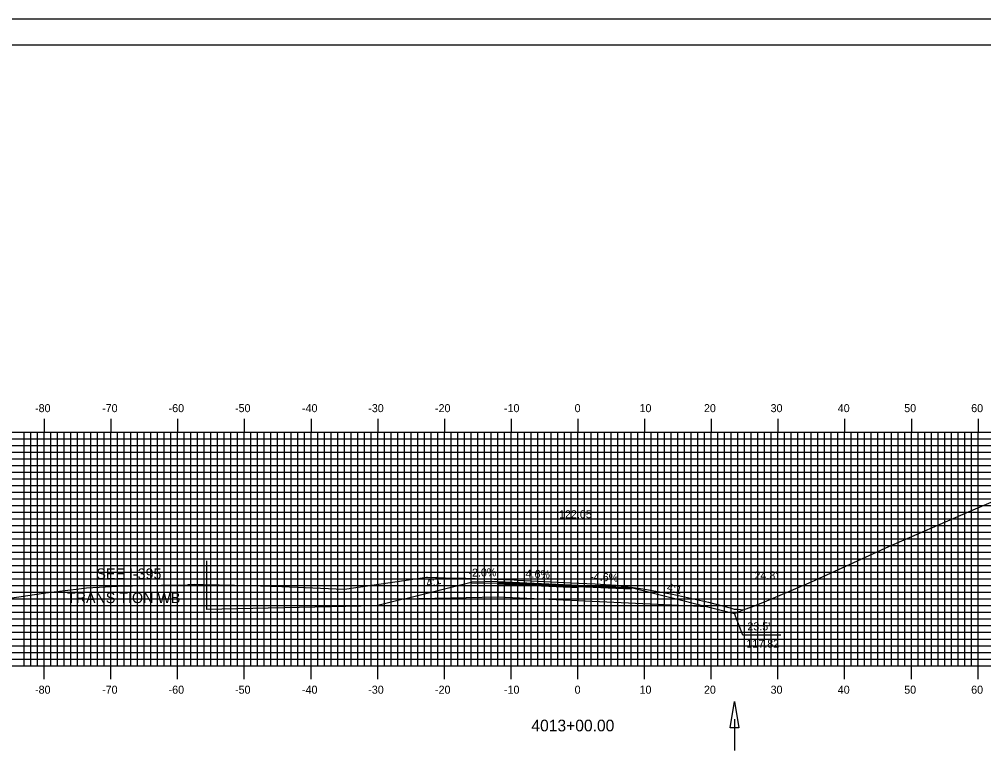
# Model space of a CAD drawing. Extents: x 852934 to 853277, y 364661 to 364881.
# Drawn here: x 853016 to 853160.6, y 364770.1 to 364881.3 of the extents above; entities that cross this region are included whole.
import ezdxf

# ---------------------------------------------------------------- set-up
doc = ezdxf.new("R2010")
doc.units = 0
for name, color, linetype in [('ANNOTATION', 7, 'Continuous'), ('BORDER', 7, 'Continuous'), ('D_Drainage_Ditch_Line', 7, 'Continuous'), ('D_Roadway_Centerline_Text', 7, 'Continuous'), ('D_Roadway_Edge_Shoulder', 7, 'Continuous'), ('D_Roadway_Edge_TW', 7, 'Continuous'), ('D_Roadway_Pavement', 7, 'Continuous'), ('D_Roadway_SubGrade', 7, 'Continuous'), ('D_Text_Standard', 7, 'Continuous'), ('H_V ANNOTATION', 7, 'Continuous'), ('M_Roadway_Centerline', 7, 'Continuous'), ('MAJOR', 7, 'Continuous'), ('MINOR', 7, 'Continuous'), ('PLOT BOUNDARY', 7, 'Continuous'), ('S_Roadway_Centerline', 7, 'Continuous')]:
    doc.layers.add(name, color=color, linetype=linetype)

msp = doc.modelspace()

# ---------------------------------------------------------------- linework, layer by layer
at = {"layer": 'ANNOTATION'}
for points in [[(853073.58, 364794.36), (853069.58, 364793.36), (853044.11, 364792.8)], [(853119.29, 364793.19), (853123.29, 364792.19), (853124.57, 364792.74)], [(853130.2, 364788.95), (853124.51, 364788.95), (853123.29, 364792.19)]]:
    msp.add_lwpolyline(points, dxfattribs=at)
at = {"layer": 'BORDER'}
msp.add_lwpolyline([(852950.18, 364667.37), (853270.18, 364667.37), (853270.18, 364877.37), (852950.18, 364877.37)], close=True, dxfattribs=at)
at = {"layer": 'D_Drainage_Ditch_Line'}
msp.add_line((853123.29, 364776.37), (853123.29, 364771.67), dxfattribs=at)
msp.add_lwpolyline([(853123.94, 364775.06), (853122.63, 364775.06), (853123.29, 364778.99)], close=True, dxfattribs=at)
at = {"layer": 'D_Roadway_Edge_Shoulder'}
for points in [[(853087.78, 364796.99), (853083.78, 364796.91), (853083.78, 364796.74), (853087.78, 364796.81)], [(853099.78, 364796.44), (853107.78, 364796.07), (853107.78, 364795.9), (853099.78, 364796.25)]]:
    msp.add_lwpolyline(points, close=True, dxfattribs=at)
at = {"layer": 'D_Roadway_Edge_TW'}
msp.add_lwpolyline([(853087.78, 364796.99), (853099.78, 364796.44), (853099.78, 364796.25), (853087.78, 364796.81)], close=True, dxfattribs=at)
at = {"layer": 'D_Roadway_Pavement'}
msp.add_lwpolyline([(853087.78, 364796.81), (853099.78, 364796.25), (853099.78, 364796.09), (853087.78, 364796.64)], close=True, dxfattribs=at)
for points in [[(853087.78, 364796.81), (853087.78, 364796.64)], [(853099.78, 364796.25), (853099.78, 364796.09)], [(853099.78, 364796.25), (853099.78, 364796.09)]]:
    msp.add_lwpolyline(points, dxfattribs=at)
at = {"layer": 'D_Roadway_SubGrade'}
msp.add_line((853044.11, 364800.1), (853044.11, 364792.8), dxfattribs=at)
for points in [[(853087.78, 364794.64), (853073.58, 364794.36), (853083.78, 364796.91), (853083.78, 364796.74), (853087.78, 364796.81), (853087.78, 364796.64)], [(853087.78, 364796.64), (853099.78, 364796.09), (853099.78, 364794.09), (853087.78, 364794.64)], [(853099.78, 364796.09), (853099.78, 364796.25), (853107.78, 364795.9), (853107.78, 364796.07), (853119.29, 364793.19), (853099.78, 364794.09)]]:
    msp.add_lwpolyline(points, close=True, dxfattribs=at)
at = {"layer": 'MAJOR'}
for p, q in [((853019.78, 364821.37), (853019.78, 364819.37)), ((853029.78, 364821.37), (853029.78, 364819.37)), ((853039.78, 364821.37), (853039.78, 364819.37)), ((853049.78, 364821.37), (853049.78, 364819.37)), ((853059.78, 364821.37), (853059.78, 364819.37)), ((853069.78, 364821.37), (853069.78, 364819.37)), ((853079.78, 364821.37), (853079.78, 364819.37)), ((853089.78, 364821.37), (853089.78, 364819.37)), ((853099.78, 364821.37), (853099.78, 364819.37)), ((853109.78, 364821.37), (853109.78, 364819.37)), ((853119.78, 364821.37), (853119.78, 364819.37)), ((853129.78, 364821.37), (853129.78, 364819.37)), ((853139.78, 364821.37), (853139.78, 364819.37)), ((853149.78, 364821.37), (853149.78, 364819.37)), ((853159.78, 364821.37), (853159.78, 364819.37)), ((852959.78, 364819.37), (853239.78, 364819.37)), ((852959.78, 364819.37), (853239.78, 364819.37)), ((853019.78, 364784.37), (853019.78, 364819.37)), ((853029.78, 364784.37), (853029.78, 364819.37)), ((853039.78, 364784.37), (853039.78, 364819.37)), ((853049.78, 364784.37), (853049.78, 364819.37)), ((853059.78, 364784.37), (853059.78, 364819.37)), ((853069.78, 364784.37), (853069.78, 364819.37)), ((853079.78, 364784.37), (853079.78, 364819.37)), ((853089.78, 364784.37), (853089.78, 364819.37)), ((853099.78, 364784.37), (853099.78, 364819.37)), ((853109.78, 364784.37), (853109.78, 364819.37)), ((853119.78, 364784.37), (853119.78, 364819.37)), ((853129.78, 364784.37), (853129.78, 364819.37)), ((853139.78, 364784.37), (853139.78, 364819.37)), ((853149.78, 364784.37), (853149.78, 364819.37)), ((853159.78, 364784.37), (853159.78, 364819.37)), ((852959.78, 364814.37), (853239.78, 364814.37)), ((852959.78, 364809.37), (853239.78, 364809.37)), ((852959.78, 364804.37), (853239.78, 364804.37)), ((852959.78, 364799.37), (853239.78, 364799.37)), ((852959.78, 364794.37), (853239.78, 364794.37)), ((852959.78, 364789.37), (853239.78, 364789.37)), ((852959.78, 364784.37), (853239.78, 364784.37)), ((852959.78, 364784.37), (853239.78, 364784.37)), ((853019.78, 364782.37), (853019.78, 364784.37)), ((853029.78, 364782.37), (853029.78, 364784.37)), ((853039.78, 364782.37), (853039.78, 364784.37)), ((853049.78, 364782.37), (853049.78, 364784.37)), ((853059.78, 364782.37), (853059.78, 364784.37)), ((853069.78, 364782.37), (853069.78, 364784.37)), ((853079.78, 364782.37), (853079.78, 364784.37)), ((853089.78, 364782.37), (853089.78, 364784.37)), ((853099.78, 364782.37), (853099.78, 364784.37)), ((853109.78, 364782.37), (853109.78, 364784.37)), ((853119.78, 364782.37), (853119.78, 364784.37)), ((853129.78, 364782.37), (853129.78, 364784.37)), ((853139.78, 364782.37), (853139.78, 364784.37)), ((853149.78, 364782.37), (853149.78, 364784.37)), ((853159.78, 364782.37), (853159.78, 364784.37))]:
    msp.add_line(p, q, dxfattribs=at)
at = {"layer": 'MINOR'}
for p, q in [((853016.78, 364784.37), (853016.78, 364819.37)), ((853017.78, 364784.37), (853017.78, 364819.37)), ((853018.78, 364784.37), (853018.78, 364819.37)), ((853020.78, 364784.37), (853020.78, 364819.37)), ((853021.78, 364784.37), (853021.78, 364819.37)), ((853022.78, 364784.37), (853022.78, 364819.37)), ((853023.78, 364784.37), (853023.78, 364819.37)), ((853024.78, 364784.37), (853024.78, 364819.37)), ((853025.78, 364784.37), (853025.78, 364819.37)), ((853026.78, 364784.37), (853026.78, 364819.37)), ((853027.78, 364784.37), (853027.78, 364819.37)), ((853028.78, 364784.37), (853028.78, 364819.37)), ((853030.78, 364784.37), (853030.78, 364819.37)), ((853031.78, 364784.37), (853031.78, 364819.37)), ((853032.78, 364784.37), (853032.78, 364819.37)), ((853033.78, 364784.37), (853033.78, 364819.37)), ((853034.78, 364784.37), (853034.78, 364819.37)), ((853035.78, 364784.37), (853035.78, 364819.37)), ((853036.78, 364784.37), (853036.78, 364819.37)), ((853037.78, 364784.37), (853037.78, 364819.37)), ((853038.78, 364784.37), (853038.78, 364819.37)), ((853040.78, 364784.37), (853040.78, 364819.37)), ((853041.78, 364784.37), (853041.78, 364819.37)), ((853042.78, 364784.37), (853042.78, 364819.37)), ((853043.78, 364784.37), (853043.78, 364819.37)), ((853044.78, 364784.37), (853044.78, 364819.37)), ((853045.78, 364784.37), (853045.78, 364819.37)), ((853046.78, 364784.37), (853046.78, 364819.37)), ((853047.78, 364784.37), (853047.78, 364819.37)), ((853048.78, 364784.37), (853048.78, 364819.37)), ((853050.78, 364784.37), (853050.78, 364819.37)), ((853051.78, 364784.37), (853051.78, 364819.37)), ((853052.78, 364784.37), (853052.78, 364819.37)), ((853053.78, 364784.37), (853053.78, 364819.37)), ((853054.78, 364784.37), (853054.78, 364819.37)), ((853055.78, 364784.37), (853055.78, 364819.37)), ((853056.78, 364784.37), (853056.78, 364819.37)), ((853057.78, 364784.37), (853057.78, 364819.37)), ((853058.78, 364784.37), (853058.78, 364819.37)), ((853060.78, 364784.37), (853060.78, 364819.37)), ((853061.78, 364784.37), (853061.78, 364819.37)), ((853062.78, 364784.37), (853062.78, 364819.37)), ((853063.78, 364784.37), (853063.78, 364819.37)), ((853064.78, 364784.37), (853064.78, 364819.37)), ((853065.78, 364784.37), (853065.78, 364819.37)), ((853066.78, 364784.37), (853066.78, 364819.37)), ((853067.78, 364784.37), (853067.78, 364819.37)), ((853068.78, 364784.37), (853068.78, 364819.37)), ((853070.78, 364784.37), (853070.78, 364819.37)), ((853071.78, 364784.37), (853071.78, 364819.37)), ((853072.78, 364784.37), (853072.78, 364819.37)), ((853073.78, 364784.37), (853073.78, 364819.37)), ((853074.78, 364784.37), (853074.78, 364819.37)), ((853075.78, 364784.37), (853075.78, 364819.37)), ((853076.78, 364784.37), (853076.78, 364819.37)), ((853077.78, 364784.37), (853077.78, 364819.37)), ((853078.78, 364784.37), (853078.78, 364819.37)), ((853080.78, 364784.37), (853080.78, 364819.37)), ((853081.78, 364784.37), (853081.78, 364819.37)), ((853082.78, 364784.37), (853082.78, 364819.37)), ((853083.78, 364784.37), (853083.78, 364819.37)), ((853084.78, 364784.37), (853084.78, 364819.37)), ((853085.78, 364784.37), (853085.78, 364819.37)), ((853086.78, 364784.37), (853086.78, 364819.37)), ((853087.78, 364784.37), (853087.78, 364819.37)), ((853088.78, 364784.37), (853088.78, 364819.37)), ((853090.78, 364784.37), (853090.78, 364819.37)), ((853091.78, 364784.37), (853091.78, 364819.37)), ((853092.78, 364784.37), (853092.78, 364819.37)), ((853093.78, 364784.37), (853093.78, 364819.37)), ((853094.78, 364784.37), (853094.78, 364819.37)), ((853095.78, 364784.37), (853095.78, 364819.37)), ((853096.78, 364784.37), (853096.78, 364819.37)), ((853097.78, 364784.37), (853097.78, 364819.37)), ((853098.78, 364784.37), (853098.78, 364819.37)), ((853100.78, 364784.37), (853100.78, 364819.37)), ((853101.78, 364784.37), (853101.78, 364819.37)), ((853102.78, 364784.37), (853102.78, 364819.37)), ((853103.78, 364784.37), (853103.78, 364819.37)), ((853104.78, 364784.37), (853104.78, 364819.37)), ((853105.78, 364784.37), (853105.78, 364819.37)), ((853106.78, 364784.37), (853106.78, 364819.37)), ((853107.78, 364784.37), (853107.78, 364819.37)), ((853108.78, 364784.37), (853108.78, 364819.37)), ((853110.78, 364784.37), (853110.78, 364819.37)), ((853111.78, 364784.37), (853111.78, 364819.37)), ((853112.78, 364784.37), (853112.78, 364819.37)), ((853113.78, 364784.37), (853113.78, 364819.37)), ((853114.78, 364784.37), (853114.78, 364819.37)), ((853115.78, 364784.37), (853115.78, 364819.37)), ((853116.78, 364784.37), (853116.78, 364819.37)), ((853117.78, 364784.37), (853117.78, 364819.37)), ((853118.78, 364784.37), (853118.78, 364819.37)), ((853120.78, 364784.37), (853120.78, 364819.37)), ((853121.78, 364784.37), (853121.78, 364819.37)), ((853122.78, 364784.37), (853122.78, 364819.37)), ((853123.78, 364784.37), (853123.78, 364819.37)), ((853124.78, 364784.37), (853124.78, 364819.37)), ((853125.78, 364784.37), (853125.78, 364819.37)), ((853126.78, 364784.37), (853126.78, 364819.37)), ((853127.78, 364784.37), (853127.78, 364819.37)), ((853128.78, 364784.37), (853128.78, 364819.37)), ((853130.78, 364784.37), (853130.78, 364819.37)), ((853131.78, 364784.37), (853131.78, 364819.37)), ((853132.78, 364784.37), (853132.78, 364819.37)), ((853133.78, 364784.37), (853133.78, 364819.37)), ((853134.78, 364784.37), (853134.78, 364819.37)), ((853135.78, 364784.37), (853135.78, 364819.37)), ((853136.78, 364784.37), (853136.78, 364819.37)), ((853137.78, 364784.37), (853137.78, 364819.37)), ((853138.78, 364784.37), (853138.78, 364819.37)), ((853140.78, 364784.37), (853140.78, 364819.37)), ((853141.78, 364784.37), (853141.78, 364819.37)), ((853142.78, 364784.37), (853142.78, 364819.37)), ((853143.78, 364784.37), (853143.78, 364819.37)), ((853144.78, 364784.37), (853144.78, 364819.37)), ((853145.78, 364784.37), (853145.78, 364819.37)), ((853146.78, 364784.37), (853146.78, 364819.37)), ((853147.78, 364784.37), (853147.78, 364819.37)), ((853148.78, 364784.37), (853148.78, 364819.37)), ((853150.78, 364784.37), (853150.78, 364819.37)), ((853151.78, 364784.37), (853151.78, 364819.37)), ((853152.78, 364784.37), (853152.78, 364819.37)), ((853153.78, 364784.37), (853153.78, 364819.37)), ((853154.78, 364784.37), (853154.78, 364819.37)), ((853155.78, 364784.37), (853155.78, 364819.37)), ((853156.78, 364784.37), (853156.78, 364819.37)), ((853157.78, 364784.37), (853157.78, 364819.37)), ((853158.78, 364784.37), (853158.78, 364819.37)), ((852959.78, 364818.37), (853239.78, 364818.37)), ((852959.78, 364817.37), (853239.78, 364817.37)), ((852959.78, 364816.37), (853239.78, 364816.37)), ((852959.78, 364815.37), (853239.78, 364815.37)), ((852959.78, 364813.37), (853239.78, 364813.37)), ((852959.78, 364812.37), (853239.78, 364812.37)), ((852959.78, 364811.37), (853239.78, 364811.37)), ((852959.78, 364810.37), (853239.78, 364810.37)), ((852959.78, 364808.37), (853239.78, 364808.37)), ((852959.78, 364807.37), (853239.78, 364807.37)), ((852959.78, 364806.37), (853239.78, 364806.37)), ((852959.78, 364805.37), (853239.78, 364805.37)), ((852959.78, 364803.37), (853239.78, 364803.37)), ((852959.78, 364802.37), (853239.78, 364802.37)), ((852959.78, 364801.37), (853239.78, 364801.37)), ((852959.78, 364800.37), (853239.78, 364800.37)), ((852959.78, 364798.37), (853239.78, 364798.37)), ((852959.78, 364797.37), (853239.78, 364797.37)), ((852959.78, 364796.37), (853239.78, 364796.37)), ((852959.78, 364795.37), (853239.78, 364795.37)), ((852959.78, 364793.37), (853239.78, 364793.37)), ((852959.78, 364792.37), (853239.78, 364792.37)), ((852959.78, 364791.37), (853239.78, 364791.37)), ((852959.78, 364790.37), (853239.78, 364790.37)), ((852959.78, 364788.37), (853239.78, 364788.37)), ((852959.78, 364787.37), (853239.78, 364787.37)), ((852959.78, 364786.37), (853239.78, 364786.37)), ((852959.78, 364785.37), (853239.78, 364785.37))]:
    msp.add_line(p, q, dxfattribs=at)
at = {"layer": 'PLOT BOUNDARY'}
msp.add_lwpolyline([(852933.99, 364661.25), (853273.99, 364661.25), (853273.99, 364881.25), (852933.99, 364881.25)], close=True, dxfattribs=at)
at = {"layer": 'S_Roadway_Centerline'}
msp.add_lwpolyline([(853014.3, 364794.43), (853020.03, 364795.3), (853024.96, 364795.9), (853026.11, 364796.04), (853030.83, 364796.29), (853037.34, 364796.45), (853041.28, 364796.51), (853041.43, 364796.55), (853042.33, 364796.57), (853043.7, 364796.54), (853050.63, 364796.37), (853055.38, 364796.26), (853063.57, 364795.91), (853064.75, 364795.86), (853064.81, 364795.84), (853074.39, 364797.22), (853077.08, 364797.63), (853077.24, 364797.65), (853079.91, 364797.56), (853081.83, 364797.5), (853083, 364797.47), (853088.63, 364797.28), (853090.24, 364797.22), (853090.68, 364797.18), (853098.66, 364796.8), (853102.37, 364796.62), (853105.52, 364796.43), (853109.51, 364795.87), (853113.97, 364795.08), (853119.35, 364793.89), (853122.64, 364793.03), (853123.2, 364792.86), (853123.81, 364792.85), (853124.57, 364792.74), (853125.87, 364793.2), (853127.74, 364793.94), (853134.8, 364796.92), (853146.39, 364802.23), (853158.35, 364807.45), (853168.78, 364811.88)], dxfattribs=at)

# ---------------------------------------------------------------- texts
at = {"layer": 'ANNOTATION'}
for s, height, p in [('SEE I-395 ', 1.6, (853027.6, 364797.35)), ('TRANSITION WB', 1.6, (853023.19, 364793.75)), ("23.5' ", 1.2, (853125.2, 364789.67)), ('117.82', 1.2, (853125.05, 364787.07))]:
    msp.add_text(s, height=height, dxfattribs=at).set_placement(p)
for s, rotation, p in [('-2.0%', 1.1458, (853083.39, 364797.7)), ('4.6%', 357.3663, (853091.93, 364797.6)), ('4:1', 14.0362, (853077.21, 364796.13)), ('-4.6%', 357.3663, (853101.61, 364797.15)), ('4:1', 345.9638, (853113.04, 364795.61))]:
    msp.add_text(s, height=1.2, rotation=rotation, dxfattribs=at).set_placement(p)
at = {"layer": 'D_Roadway_Centerline_Text'}
msp.add_text('122.05', height=1.2, dxfattribs=at).set_placement((853096.96, 364806.47))
at = {"layer": 'D_Text_Standard'}
msp.add_text("24.8'", height=1.2, dxfattribs=at).set_placement((853126.26, 364797.31))
at = {"layer": 'H_V ANNOTATION'}
for s, height, p in [('-80', 1.2, (853018.41, 364822.37)), ('-70', 1.2, (853028.46, 364822.37)), ('-60', 1.2, (853038.43, 364822.37)), ('-50', 1.2, (853048.39, 364822.37)), ('-40', 1.2, (853058.43, 364822.37)), ('-30', 1.2, (853068.36, 364822.37)), ('-20', 1.2, (853078.37, 364822.37)), ('-10', 1.2, (853088.71, 364822.37)), ('0', 1.2, (853099.3, 364822.37)), ('10', 1.2, (853109.03, 364822.37)), ('20', 1.2, (853118.69, 364822.37)), ('30', 1.2, (853128.68, 364822.37)), ('40', 1.2, (853138.75, 364822.37)), ('50', 1.2, (853148.71, 364822.37)), ('60', 1.2, (853158.75, 364822.37)), ('-80', 1.2, (853018.41, 364780.17)), ('-70', 1.2, (853028.46, 364780.17)), ('-60', 1.2, (853038.43, 364780.17)), ('-50', 1.2, (853048.39, 364780.17)), ('-40', 1.2, (853058.43, 364780.17)), ('-30', 1.2, (853068.36, 364780.17)), ('-20', 1.2, (853078.37, 364780.17)), ('-10', 1.2, (853088.71, 364780.17)), ('0', 1.2, (853099.3, 364780.17)), ('10', 1.2, (853109.03, 364780.17)), ('20', 1.2, (853118.69, 364780.17)), ('30', 1.2, (853128.68, 364780.17)), ('40', 1.2, (853138.75, 364780.17)), ('50', 1.2, (853148.71, 364780.17)), ('60', 1.2, (853158.75, 364780.17)), ('4013+00.00', 1.75, (853092.82, 364774.53))]:
    msp.add_text(s, height=height, dxfattribs=at).set_placement(p)
at = {"layer": 'M_Roadway_Centerline'}
for s, p in [('C', (853042.33, 364796.57)), ('L', (853042.33, 364796.57)), ('C', (853090.23, 364797.22)), ('L', (853090.24, 364797.21))]:
    msp.add_text(s, height=0.0146, dxfattribs=at).set_placement(p)

doc.saveas('drawing.dxf')
